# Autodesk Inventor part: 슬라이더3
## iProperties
Company: 한국ATC센터
Created: 2015-04
Part Number: 슬라이더3
Document SubType Name: Modeling
Designer: KYOUNG IL JANG
Density: 1 g/cm^3
Material: 기본값
Mass: 11.8344 g
Surface Area: 43.7403 cm^2
Volume: 11.8344 cm^3
Author: KYOUNG IL JANG
